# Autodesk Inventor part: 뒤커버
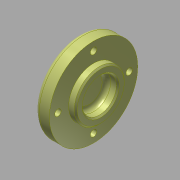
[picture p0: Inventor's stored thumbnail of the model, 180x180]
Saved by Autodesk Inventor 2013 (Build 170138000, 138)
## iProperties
Created: 2015-12
Part Number: 뒤커버
Document SubType Name: Modeling
Designer: mdu
Density: 2.71 g/cm^3
Material: 알루미늄 6061
Mass: 80.8116 g
Surface Area: 93.036 cm^2
Volume: 29.8198 cm^3
Author: mdu
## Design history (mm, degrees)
sketch "스케치1"
  geometry: L1 (-7.5, 0)-(7.5, 0); L2 (-7.5, 0)-(-7.5, 31); L3 (-7.5, 31)-(2.5, 31); L4 (2.5, 31)-(2.5, 17.5); L5 (2.5, 17.5)-(7.5, 17.5); L6 (7.5, 17.5)-(7.5, 0); 2 further points
  constraints: 12 end point, 3 parallel, 1 coincident, 1 horizontal, 1 midpoint, 1 perpendicular
  dimensions: "d0" = 15 distance of L1.start L1.end; "d1" = 62 diameter of L3 L1; "d2" = 35 diameter of L5 L1; "d34" = 10 distance of L2.end L3.end
revolve "회전1" sketch "스케치1" stored, may be unused: angle "d6" = 90 deg
sketch "스케치2" dims "d32" = 50
  geometry: 3 further points
  constraints: 2 vertical alignment, 1 coincident, 2 other
hole "구멍1" sketch "스케치2" at (0, 25) diameter "d8" = 4.5; stored, may be unused: countersink angle "d12" = 90 deg, drill point angle "d14" = 118 deg; dims "d9" = 6, "d10" = 8, "d11" = 4.4, "d13" = 8
hole "구멍2" diameter "d20" = 24; stored, may be unused: countersink angle "d24" = 90 deg, drill point angle "d26" = 0 deg; dims "d18" = 10, "d19" = 10, "d21" = 6, "d22" = 8, "d23" = 4.4, "d25" = 8
fillet "모깎기1" dims "d27" = 3
fillet "모깎기2" dims "d28" = 3
chamfer "모따기1" distance "d29" = 1; stored, may be unused: second distance "d30" = 2, angle "d31" = 45 deg
node "솔리드1"
pattern_circular "원형 패턴1" dims angle "d16" = 360 deg
